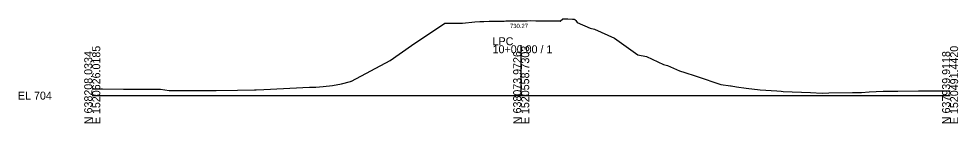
# Model space of a CAD drawing. Extents: x -26 to 303, y -10 to 4521.
# Drawn here: x -25.7 to 302.8, y -9.7 to 27 of the extents above; entities that cross this region are included whole.
import ezdxf

# ---------------------------------------------------------------- set-up
doc = ezdxf.new("R2010")
doc.units = 0
for name, color, linetype in [('Default', 7, 'Continuous'), ('Exist Cross Section Cell', 7, 'Continuous'), ('Exist XS Center Line Elevation Label', 7, 'Continuous'), ('Exist XS Ground Line', 7, 'Continuous')]:
    doc.layers.add(name, color=color, linetype=linetype)

msp = doc.modelspace()

# ---------------------------------------------------------------- linework, layer by layer
at = {"layer": 'Exist Cross Section Cell'}
for p, q in [((150, 0), (150, 17.66)), ((0, 0), (150, 0)), ((150, 0), (300, 0))]:
    msp.add_line(p, q, dxfattribs=at)
at = {"layer": 'Exist XS Ground Line'}
msp.add_lwpolyline([(0, 2.38), (3.61, 2.37), (10.94, 2.24), (23.91, 2.23), (26.84, 1.81), (27.06, 1.81), (41.8, 1.8), (43.37, 1.77), (50.75, 1.88), (56.71, 1.99), (57.32, 2.02), (60.04, 2.2), (75.95, 2.94), (78.19, 2.95), (80.74, 3.16), (84.01, 3.56), (87.11, 4.11), (90.29, 5.01), (90.54, 5.07), (90.63, 5.12), (104.21, 12.28), (111.62, 17.61), (123.26, 25.36), (123.32, 25.37), (129.47, 25.38), (133.8, 25.84), (135.56, 26.02), (136.47, 26.03), (136.93, 26.04), (136.94, 26.05), (138.77, 26.08), (139.39, 26.09), (140.94, 26.13), (142.17, 26.16), (144.04, 26.17), (144.67, 26.18), (144.98, 26.18), (146.52, 26.2), (147.76, 26.23), (148.57, 26.25), (149.22, 26.27), (150.12, 26.28), (150.53, 26.28), (152.09, 26.28), (153.34, 26.29), (155.16, 26.28), (155.81, 26.28), (156.13, 26.28), (157.11, 26.27), (158.94, 26.24), (160.72, 26.22), (161.7, 26.21), (162.52, 26.22), (162.53, 26.22), (162.64, 26.22), (163.44, 26.22), (163.65, 26.14), (164.55, 26.91), (164.62, 26.96), (164.63, 26.97), (164.64, 26.96), (164.66, 26.96), (166.31, 26.88), (168, 26.79), (168.35, 26.77), (168.58, 26.76), (168.7, 26.75), (168.78, 26.74), (169.09, 26.3), (169.57, 25.66), (174.11, 23.7), (175.61, 23.33), (182.67, 20.21), (190.78, 14.35), (193.82, 13.72), (199.73, 10.88), (201.18, 10.51), (205.42, 8.72), (206.04, 8.49), (206.48, 8.36), (211.49, 6.76), (219.77, 3.93), (223.2, 3.43), (223.42, 3.39), (225.25, 3.11), (228.67, 2.61), (233.6, 2.05), (239.4, 1.64), (240.91, 1.55), (241.65, 1.5), (251.15, 1.07), (255.21, 0.89), (257.57, 1), (265.86, 1.05), (266.57, 1.06), (268.98, 1.09), (271.74, 1.28), (276.63, 1.51), (281.73, 1.61), (288.96, 1.73), (289.01, 1.73), (289.03, 1.73), (289.09, 1.73), (291.75, 1.67), (293.35, 1.68), (295.6, 1.68), (295.76, 1.68), (296.03, 1.68), (296.91, 1.67), (297.32, 1.66), (298.52, 1.66), (299.1, 1.66), (300, 1.66)], dxfattribs=at)

# ---------------------------------------------------------------- texts
at = {"layer": 'Default'}
msp.add_text('-', height=0.0001, dxfattribs=at).set_placement((0, 0))
at = {"layer": 'Exist Cross Section Cell'}
for s, p in [('LPC', (140, 17.66)), ('10+00.00 / 1', (140, 14.86)), ('EL 704', (-26, -1.4))]:
    msp.add_text(s, height=2.8, dxfattribs=at).set_placement(p)
for s, p in [('E 1520626.0185', (2.8, -10)), ('E 1520558.7303', (152.8, -10)), ('E 1520491.4420', (302.8, -10)), ('N 638208.0334', (0, -10)), ('N 638073.9726', (150, -10)), ('N 637939.9118', (300, -10))]:
    msp.add_text(s, height=2.8, rotation=90, dxfattribs=at).set_placement(p)
at = {"layer": 'Exist XS Center Line Elevation Label'}
msp.add_text('730.27', height=1.5, dxfattribs=at).set_placement((146.07, 23.69))

doc.saveas('drawing.dxf')
